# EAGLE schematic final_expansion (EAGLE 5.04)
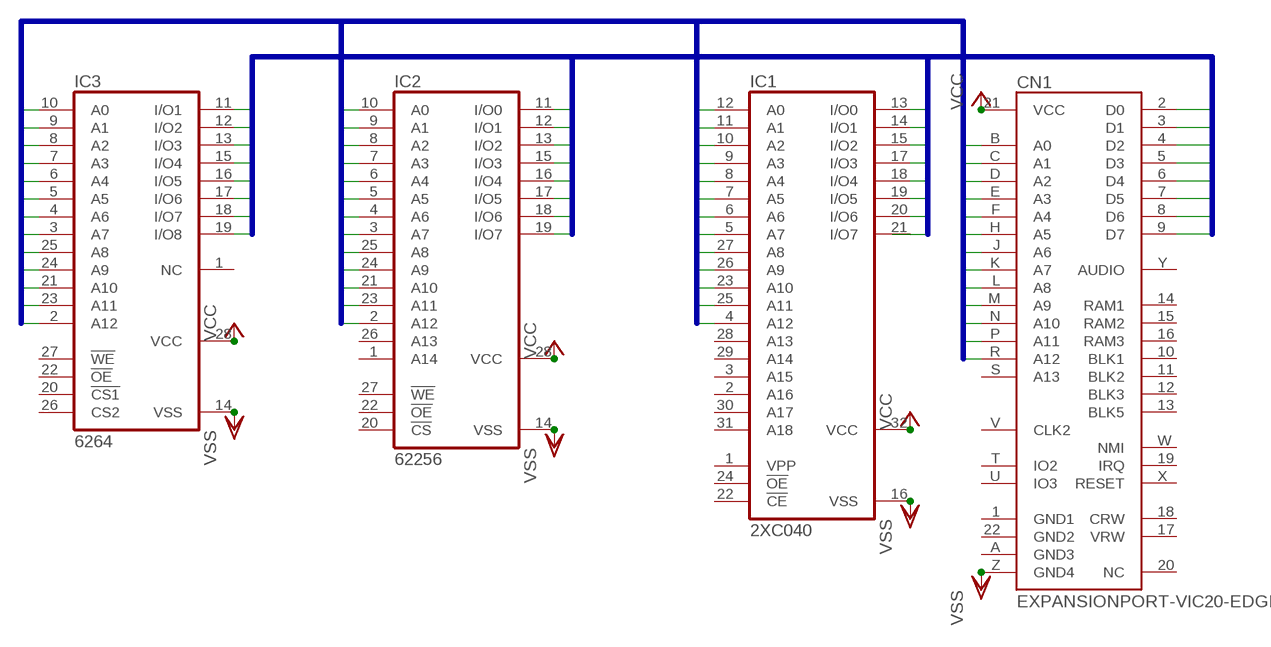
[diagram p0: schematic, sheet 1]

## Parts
CN1  EXPANSIONPORT-VIC20-EDGE  [UPS44EDGE]
IC1  2XC040  27C4001G  [DIL32]
IC2  62256  62256P  [DIL28-6]
IC3  6264  6264A  [DIL28-6]

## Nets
A0: CN1.B(A0) IC1.12(A0) IC2.10(A0) IC3.10(A0)
A1: CN1.C(A1) IC1.11(A1) IC2.9(A1) IC3.9(A1)
A2: CN1.D(A2) IC1.10(A2) IC2.8(A2) IC3.8(A2)
A3: CN1.E(A3) IC1.9(A3) IC2.7(A3) IC3.7(A3)
A4: CN1.F(A4) IC1.8(A4) IC2.6(A4) IC3.6(A4)
A5: CN1.H(A5) IC1.7(A5) IC2.5(A5) IC3.5(A5)
A6: CN1.J(A6) IC1.6(A6) IC2.4(A6) IC3.4(A6)
A7: CN1.K(A7) IC1.5(A7) IC2.3(A7) IC3.3(A7)
A8: CN1.L(A8) IC1.27(A8) IC2.25(A8) IC3.25(A8)
A9: CN1.M(A9) IC1.26(A9) IC2.24(A9) IC3.24(A9)
A10: CN1.N(A10) IC1.23(A10) IC2.21(A10) IC3.21(A10)
A11: CN1.P(A11) IC1.25(A11) IC2.23(A11) IC3.23(A11)
A12: CN1.R(A12) IC1.4(A12) IC2.2(A12) IC3.2(A12)
D0: CN1.2(D0) IC1.13(I/O0) IC2.11(I/O0) IC3.11(I/O1)
D1: CN1.3(D1) IC1.14(I/O1) IC2.12(I/O1) IC3.12(I/O2)
D2: CN1.4(D2) IC1.15(I/O2) IC2.13(I/O2) IC3.13(I/O3)
D3: CN1.5(D3) IC1.17(I/O3) IC2.15(I/O3) IC3.15(I/O4)
D4: CN1.6(D4) IC1.18(I/O4) IC2.16(I/O4) IC3.16(I/O5)
D5: CN1.7(D5) IC1.19(I/O5) IC2.17(I/O5) IC3.17(I/O6)
D6: CN1.8(D6) IC1.20(I/O6) IC2.18(I/O6) IC3.18(I/O7)
D7: CN1.9(D7) IC2.19(I/O7) IC3.19(I/O8)
VCC: CN1.21(VCC) IC1.32(VCC) IC2.28(VCC) IC3.28(VCC)
VSS: CN1.Z(GND4) IC1.16(VSS) IC2.14(VSS) IC3.14(VSS)
Unconnected: CN1.1(GND1) CN1.10(BLK1) CN1.11(BLK2) CN1.12(BLK3) CN1.13(BLK5) CN1.14(RAM1) CN1.15(RAM2) CN1.16(RAM3) CN1.17(VRW) CN1.18(CRW) CN1.19(IRQ) CN1.20(NC) CN1.22(GND2) CN1.A(GND3) CN1.S(A13) CN1.T(IO2) CN1.U(IO3) CN1.V(CLK2) CN1.W(NMI) CN1.X(RESET) CN1.Y(AUDIO) IC1.1(VPP) IC1.2(A16) IC1.3(A15) IC1.21(I/O7) IC1.22(!CE) IC1.24(!OE) IC1.28(A13) IC1.29(A14) IC1.30(A17) IC1.31(A18) IC2.1(A14) IC2.20(!CS) IC2.22(!OE) IC2.26(A13) IC2.27(!WE) IC3.1(NC) IC3.20(!CS1) IC3.22(!OE) IC3.26(CS2) IC3.27(!WE)

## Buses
D[0..7]
A[0..12]

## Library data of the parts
CN1 = 0RB_Commodore:EXPANSIONPORT-VIC20-EDGE: Expansionport of the Commodore VIC-20
IC1 = memory-hitachi:27C4001G: MEMORY
IC2 = memory-hitachi:62256P: MEMORY
IC3 = memory-hitachi:6264A: MEMORY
